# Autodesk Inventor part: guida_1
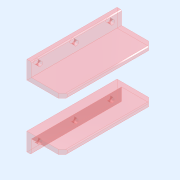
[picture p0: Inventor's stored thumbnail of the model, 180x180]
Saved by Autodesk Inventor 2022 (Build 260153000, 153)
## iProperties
Created: 2022-01
Part Number: guida_1
Material: Generico
Document SubType Name: Modeling
Designer: admin
Density: 1 g/cm^3
Appearance: Rosso scuro
Author: admin
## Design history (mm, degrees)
sketch "Schizzo1"
  geometry: L1 (0, 0)-(0, -107) reference; L2 (40, -28)-(0, -28); L3 (0, -28)-(0, -23); L4 (0, -23)-(40, -23); L5 (40, -23)-(40, -28); L6 (0, -77)-(0, -82); L7 (0, -82)-(40, -82); L8 (40, -82)-(40, -77); L9 (0, -23)-(5, -23); L10 (5, -23)-(5, -8); L11 (5, -8)-(0, -8); L12 (0, -8)-(0, -23); L13 (0, -82)-(5, -82); L14 (5, -82)-(5, -97); L15 (5, -97)-(0, -97); L16 (0, -97)-(0, -82); L17 (40, -77)-(0, -77); 6 further points
  constraints: 32 end point, 8 parallel, 3 horizontal, 3 perpendicular, 3 point on line
  dimensions: "d0" = 5 distance of L2.end L3.end; "d1" = 5 distance of L6.end L6.start; "d2" = 5 distance of L11.end L10.end; "d3" = 15 distance of L10.end L9.end; "d4" = 15 distance of L13.end L14.end; "d7" = 40 distance of L2.start L2.end; "d8" = 40 distance of L8.end L6.start
extrude "Estrusione1" new body sketch "Schizzo1" distance "d5" = 100; taper "d6" = 0 deg
sketch "Schizzo2"
  geometry: L1 (100, 15)-(100, 0) reference; L2 (0, 15)-(100, 15) reference; L3 (100, -5)-(100, 15) reference; L4 (100, 8)-(0, 8); L5 (50, 8)-(50, 23); C1 r 2.5 at (90, 8); C2 r 2.5 at (50, 8); C3 r 2.5 at (10, 8); 1 further point
  constraints: 4 end point, 3 centre point, 1 horizontal, 1 midpoint, 1 point on line, 1 symmetric about line, 1 vertical, 1 other
  dimensions: "d9" = 5 diameter of C1; "d10" = 10 distance from line of L1 C1.centre; "d11" = 7 distance from line of L2 C1.centre; "d12" = 5 diameter of C2
extrude "Estrusione2" cut sketch "Schizzo2" extent not by distance; stored distance "d13" = 0; taper "d14" = 0 deg
node "Piano di lavoro1"
mirror "Specchio1"
chamfer "Smusso1" distance "d15" = 1; stored, may be unused: second distance "d16" = 2, angle "d17" = 45 deg
chamfer "Smusso2" distance "d18" = 5; stored, may be unused: second distance "d19" = 2, angle "d20" = 45 deg
node "Solido1"
node "Riferimento4"
